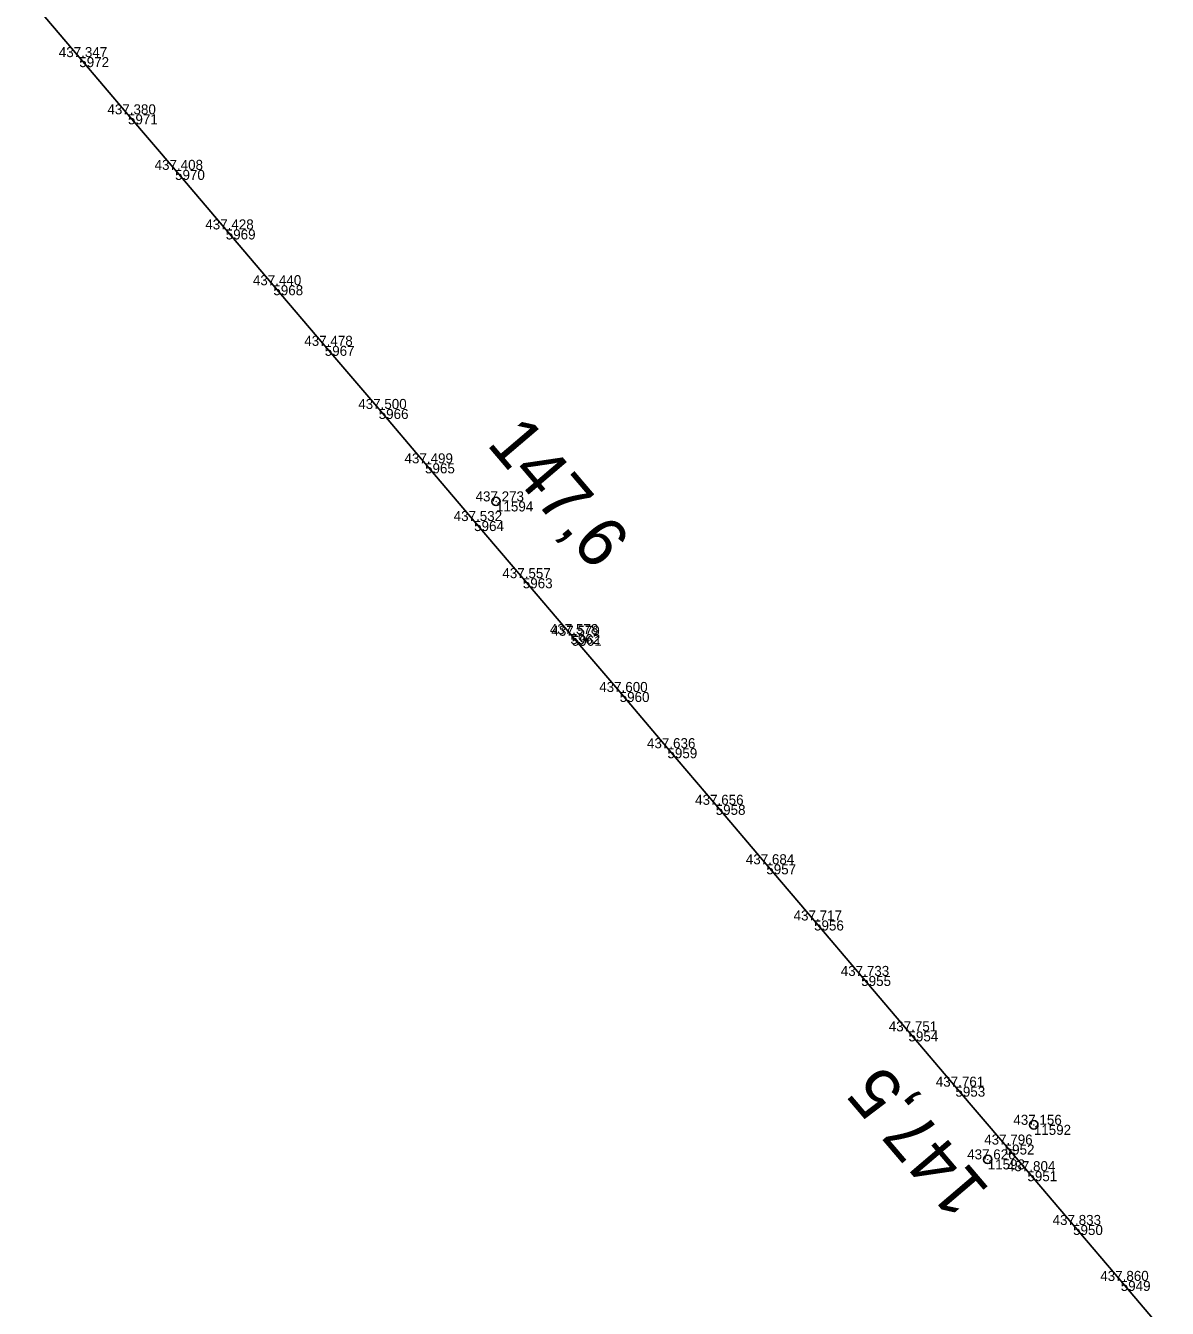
# Model space of a CAD drawing. Extents: x -654154 to -652650, y -1166925 to -1164904.
# Drawn here: x -654027.1 to -653890.3, y -1165209.7 to -1165056.1 of the extents above; entities that cross this region are included whole.
import ezdxf

# ---------------------------------------------------------------- set-up
doc = ezdxf.new("R2010")
doc.units = 0
for name, color, linetype in [('Vrstva 1', 7, 'Continuous'), ('Vrstva 50', 7, 'Continuous'), ('Vrstva 60', 7, 'Continuous'), ('Vrstva 61', 7, 'Continuous'), ('Vrstva 7', 7, 'Continuous')]:
    doc.layers.add(name, color=color, linetype=linetype)

msp = doc.modelspace()

# ---------------------------------------------------------------- linework, layer by layer
at = {"layer": 'Vrstva 1'}
msp.add_lwpolyline([(-653890.35, -1165213.02), (-653895.93, -1165206.45), (-653901.64, -1165199.75), (-653907.11, -1165193.31), (-653909.83, -1165190.12), (-653915.73, -1165183.19), (-653921.35, -1165176.57), (-653927.01, -1165169.93), (-653932.66, -1165163.29), (-653938.38, -1165156.56), (-653944.44, -1165149.44), (-653950.22, -1165142.66), (-653955.94, -1165135.93), (-653961.67, -1165129.2), (-653961.84, -1165129), (-653967.54, -1165122.3), (-653973.37, -1165115.46), (-653979.25, -1165108.55), (-653984.8, -1165102.04), (-653991.26, -1165094.48), (-653997.42, -1165087.22), (-654003.12, -1165080.54), (-654009.19, -1165073.41), (-654014.83, -1165066.76), (-654020.66, -1165059.91), (-654027.08, -1165052.37)], dxfattribs=at)
at = {"layer": 'Vrstva 50'}
msp.add_line((-653906.39, -1165187.76), (-653906.29, -1165187.76), dxfattribs=at)
msp.add_circle((-653906.34, -1165187.76), 0.5, dxfattribs=at)
at = {"layer": 'Vrstva 60'}
for p, q in [((-654020.66, -1165059.91), (-654020.66, -1165059.91)), ((-654014.83, -1165066.76), (-654014.83, -1165066.76)), ((-654009.19, -1165073.41), (-654009.19, -1165073.41)), ((-654003.12, -1165080.54), (-654003.12, -1165080.54)), ((-653997.42, -1165087.22), (-653997.42, -1165087.22)), ((-653991.26, -1165094.48), (-653991.26, -1165094.48)), ((-653984.8, -1165102.04), (-653984.8, -1165102.04)), ((-653979.25, -1165108.55), (-653979.25, -1165108.55)), ((-653970.75, -1165113.11), (-653970.75, -1165113.11)), ((-653973.37, -1165115.46), (-653973.37, -1165115.46)), ((-653967.54, -1165122.3), (-653967.54, -1165122.3)), ((-653961.84, -1165129), (-653961.84, -1165129)), ((-653961.67, -1165129.2), (-653961.67, -1165129.2)), ((-653955.94, -1165135.93), (-653955.94, -1165135.93)), ((-653950.22, -1165142.66), (-653950.22, -1165142.66)), ((-653944.44, -1165149.44), (-653944.44, -1165149.44)), ((-653938.38, -1165156.56), (-653938.38, -1165156.56)), ((-653932.66, -1165163.29), (-653932.66, -1165163.29)), ((-653927.01, -1165169.93), (-653927.01, -1165169.93)), ((-653921.35, -1165176.57), (-653921.35, -1165176.57)), ((-653915.73, -1165183.19), (-653915.73, -1165183.19)), ((-653906.34, -1165187.76), (-653906.34, -1165187.76)), ((-653909.83, -1165190.12), (-653909.83, -1165190.12)), ((-653911.86, -1165191.9), (-653911.86, -1165191.9)), ((-653907.11, -1165193.31), (-653907.11, -1165193.31)), ((-653901.64, -1165199.75), (-653901.64, -1165199.75)), ((-653895.93, -1165206.45), (-653895.93, -1165206.45))]:
    msp.add_line(p, q, dxfattribs=at)
at = {"layer": 'Vrstva 7'}
for p, q in [((-653970.78, -1165113.07), (-653970.71, -1165113.15)), ((-653911.83, -1165191.94), (-653911.9, -1165191.86))]:
    msp.add_line(p, q, dxfattribs=at)
for centre in [(-653970.75, -1165113.11), (-653911.86, -1165191.9)]:
    msp.add_circle(centre, 0.5, dxfattribs=at)

# ---------------------------------------------------------------- texts
at = {"layer": 'Vrstva 60'}
for s, p in [('5972', (-654020.66, -1165061.11)), ('5971', (-654014.83, -1165067.96)), ('5970', (-654009.19, -1165074.61)), ('5969', (-654003.12, -1165081.74)), ('5968', (-653997.42, -1165088.42)), ('5967', (-653991.26, -1165095.68)), ('5966', (-653984.8, -1165103.24)), ('5965', (-653979.25, -1165109.75)), ('11594', (-653970.75, -1165114.31)), ('5964', (-653973.37, -1165116.66)), ('5963', (-653967.54, -1165123.51)), ('5962', (-653961.84, -1165130.2)), ('5961', (-653961.67, -1165130.4)), ('5960', (-653955.94, -1165137.13)), ('5959', (-653950.22, -1165143.86)), ('5958', (-653944.44, -1165150.64)), ('5957', (-653938.38, -1165157.76)), ('5956', (-653932.66, -1165164.49)), ('5955', (-653927.01, -1165171.13)), ('5954', (-653921.35, -1165177.77)), ('5953', (-653915.73, -1165184.39)), ('11592', (-653906.34, -1165188.96)), ('5952', (-653909.83, -1165191.32)), ('11593', (-653911.86, -1165193.1)), ('5951', (-653907.11, -1165194.51)), ('5950', (-653901.64, -1165200.95)), ('5949', (-653895.93, -1165207.65))]:
    msp.add_text(s, height=1.2, dxfattribs=at).set_placement(p)
at = {"layer": 'Vrstva 61'}
for s, p in [('437.347', (-654023.11, -1165059.91)), ('437.380', (-654017.29, -1165066.76)), ('437.408', (-654011.64, -1165073.41)), ('437.428', (-654005.57, -1165080.54)), ('437.440', (-653999.87, -1165087.22)), ('437.478', (-653993.71, -1165094.48)), ('437.500', (-653987.25, -1165102.04)), ('437.499', (-653981.71, -1165108.55)), ('437.273', (-653973.2, -1165113.11)), ('437.532', (-653975.82, -1165115.46)), ('437.557', (-653969.99, -1165122.3)), ('437.578', (-653964.3, -1165129)), ('437.579', (-653964.12, -1165129.2)), ('437.600', (-653958.39, -1165135.93)), ('437.636', (-653952.67, -1165142.66)), ('437.656', (-653946.9, -1165149.44)), ('437.684', (-653940.83, -1165156.56)), ('437.717', (-653935.11, -1165163.29)), ('437.733', (-653929.46, -1165169.93)), ('437.751', (-653923.71, -1165176.57)), ('437.761', (-653918.08, -1165183.19)), ('437.156', (-653908.79, -1165187.76)), ('437.796', (-653912.28, -1165190.12)), ('437.626', (-653914.32, -1165191.9)), ('437.804', (-653909.56, -1165193.31)), ('437.833', (-653904.09, -1165199.75)), ('437.860', (-653898.38, -1165206.45))]:
    msp.add_text(s, height=1.2, dxfattribs=at).set_placement(p)
at = {"layer": 'Vrstva 7'}
for s, rotation, p in [('147,6', 310.4002, (-653971.97, -1165106.26)), ('147,5', 130.435, (-653911.48, -1165195.58))]:
    msp.add_text(s, height=6, rotation=rotation, dxfattribs=at).set_placement(p)

doc.saveas('drawing.dxf')
